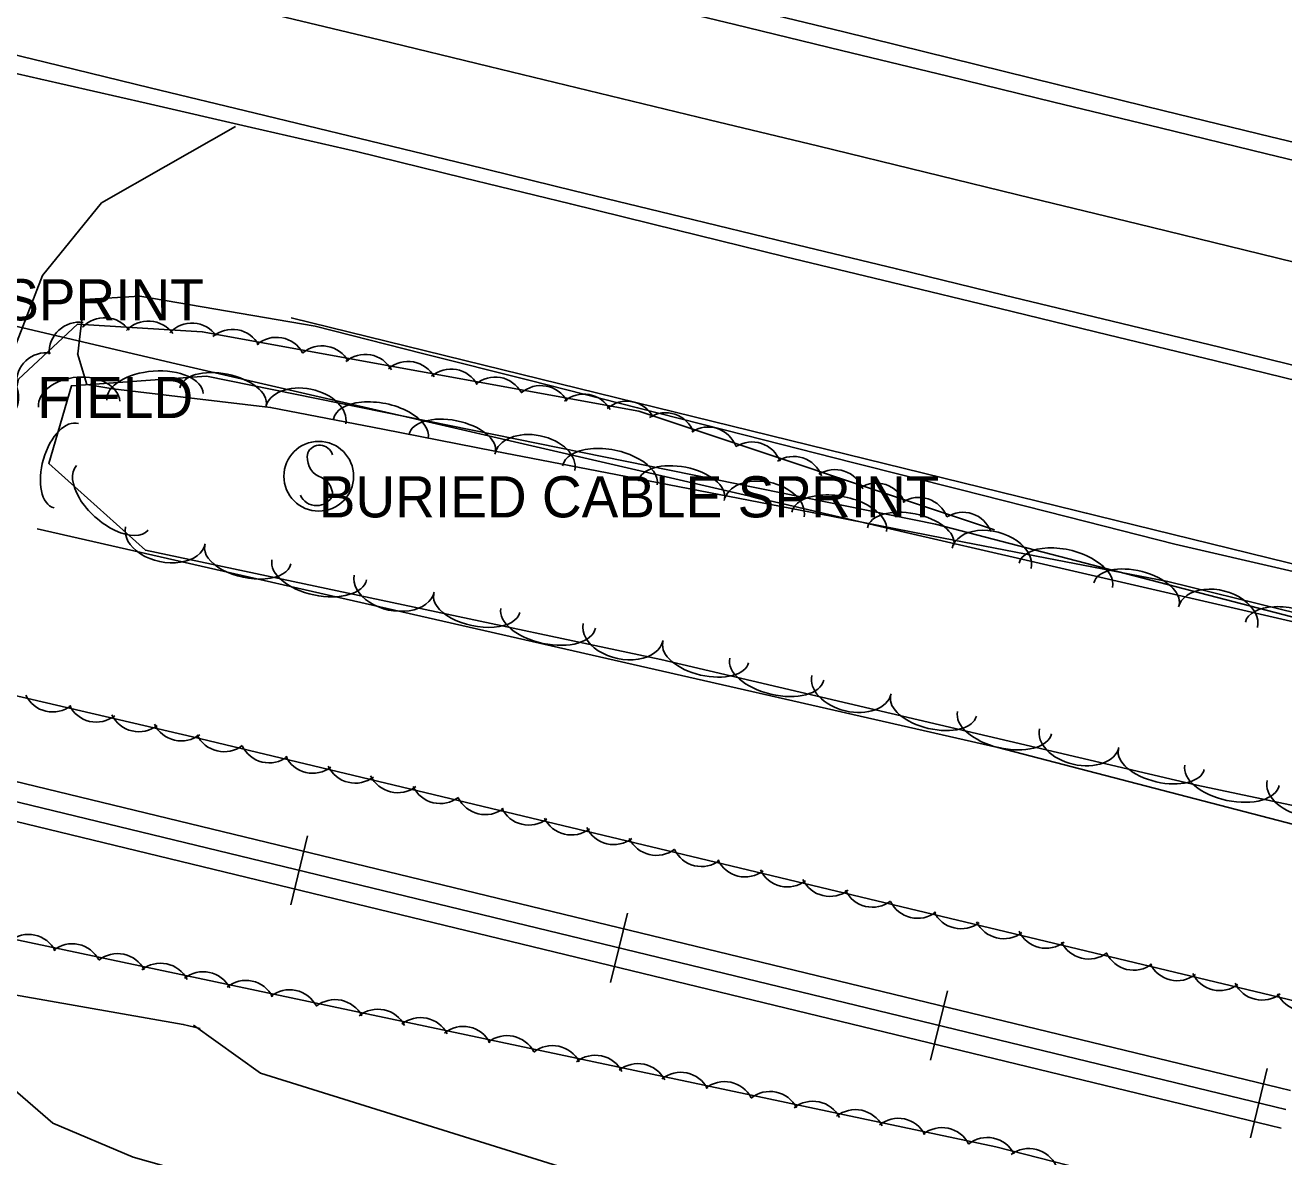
# Model space of a CAD drawing. Extents: x 1441650 to 1491889, y 345904 to 358319.
# Drawn here: x 1454238.7 to 1454391.6, y 352365.8 to 352503.4 of the extents above; entities that cross this region are included whole.
import ezdxf

# ---------------------------------------------------------------- set-up
doc = ezdxf.new("R2010")
doc.units = 0
for name, color, linetype in [('S_DITCHLINE', 7, 'Continuous'), ('S_EDGE_PAVEMENT', 7, 'Continuous'), ('S_GRAVEL_ROAD', 7, 'Continuous'), ('S_PAVEMENT_CROWN', 7, 'Continuous'), ('S_RAILROAD', 7, 'Continuous'), ('S_SHOULDER', 7, 'Continuous'), ('S_SIGN', 7, 'Continuous'), ('S_SIGN_ANNOT', 7, 'Continuous'), ('S_STREAM', 7, 'Continuous'), ('S_SURVEY_TEXT_ANNOT', 7, 'Continuous'), ('S_TREE', 7, 'Continuous')]:
    doc.layers.add(name, color=color, linetype=linetype)

msp = doc.modelspace()

# ---------------------------------------------------------------- linework, layer by layer
at = {"layer": 'S_DITCHLINE'}
for points in [[(1454245.06, 352463.43), (1454245.84, 352470.01), (1454252.59, 352470.4), (1454273.89, 352466.78), (1454286.95, 352463.47), (1454300.01, 352460.16), (1454313.07, 352456.85), (1454326.13, 352453.53), (1454339.19, 352450.22), (1454352.25, 352446.91), (1454365.31, 352443.6), (1454378.37, 352440.28), (1454392.2, 352437.07), (1454406.03, 352433.85), (1454419.86, 352430.64), (1454433.69, 352427.43), (1454447.53, 352424.21), (1454461.36, 352421), (1454475.19, 352417.78), (1454489.02, 352414.57), (1454502.88, 352411.14), (1454516.73, 352407.7), (1454530.58, 352404.27), (1454544.44, 352400.84)], [(1454245.03, 352463.46), (1454246.15, 352459.68), (1454249.29, 352459.16), (1454268.48, 352456.89), (1454282.11, 352454.24), (1454295.74, 352451.59), (1454309.36, 352448.95), (1454322.99, 352446.3), (1454336.62, 352443.66), (1454350.25, 352441.01), (1454363.88, 352438.36), (1454377.51, 352435.72), (1454391.33, 352432.35), (1454405.16, 352428.97), (1454418.98, 352425.6), (1454432.8, 352422.23), (1454446.63, 352418.85), (1454460.45, 352415.48), (1454474.27, 352412.11), (1454488.1, 352408.74), (1454501.74, 352404.67), (1454515.38, 352400.61), (1454529.02, 352396.55), (1454542.66, 352392.48)]]:
    msp.add_lwpolyline(points, dxfattribs=at)
at = {"layer": 'S_EDGE_PAVEMENT'}
for points in [[(1454234.14, 352525.39), (1454247.12, 352522.26), (1454260.09, 352519.12), (1454273.07, 352515.99), (1454286.04, 352512.86), (1454299, 352509.72), (1454311.95, 352506.58), (1454324.9, 352503.44), (1454337.85, 352500.29), (1454350.76, 352497.15), (1454363.67, 352494), (1454376.58, 352490.86), (1454389.49, 352487.72), (1454403.74, 352484.26), (1454417.98, 352480.8), (1454432.22, 352477.34), (1454446.47, 352473.88), (1454460.26, 352470.49), (1454474.05, 352467.09), (1454487.84, 352463.69), (1454501.63, 352460.3), (1454515.2, 352456.99), (1454528.77, 352453.68), (1454542.33, 352450.37)], [(1454228.36, 352501.94), (1454241.1, 352498.85), (1454253.85, 352495.76), (1454266.6, 352492.67), (1454279.34, 352489.58), (1454292.36, 352486.41), (1454305.38, 352483.24), (1454318.4, 352480.07), (1454331.42, 352476.9), (1454344.52, 352473.73), (1454357.63, 352470.56), (1454370.73, 352467.39), (1454383.83, 352464.22), (1454398.14, 352460.71)]]:
    msp.add_lwpolyline(points, dxfattribs=at)
at = {"layer": 'S_GRAVEL_ROAD'}
msp.add_lwpolyline([(1454228.71, 352431.22), (1454231.59, 352443.76), (1454235.46, 352459.28), (1454240.77, 352472.94), (1454247.94, 352481.75), (1454255.77, 352486.24), (1454264.22, 352491.06)], dxfattribs=at)
at = {"layer": 'S_PAVEMENT_CROWN'}
msp.add_lwpolyline([(1454232.36, 352513.43), (1454244.7, 352510.46), (1454257.04, 352507.5), (1454269.37, 352504.53), (1454281.71, 352501.57), (1454295.06, 352498.34), (1454308.41, 352495.1), (1454321.77, 352491.87), (1454335.12, 352488.64), (1454348.03, 352485.49), (1454360.94, 352482.34), (1454373.84, 352479.2), (1454386.75, 352476.05), (1454401.14, 352472.51), (1454415.53, 352468.97), (1454429.92, 352465.43), (1454444.3, 352461.89), (1454457.87, 352458.61), (1454471.44, 352455.33), (1454485.01, 352452.05), (1454498.58, 352448.77), (1454512.22, 352445.42), (1454525.86, 352442.07), (1454539.5, 352438.72)], dxfattribs=at)
at = {"layer": 'S_RAILROAD'}
for p, q in [((1454272.97, 352404.84), (1454270.92, 352396.42)), ((1454272.5, 352402.94), (1454272.5, 352402.9)), ((1454271.39, 352398.36), (1454271.42, 352398.46)), ((1454311.84, 352395.42), (1454309.8, 352386.99)), ((1454311.38, 352393.51), (1454311.37, 352393.47)), ((1454310.27, 352388.93), (1454310.29, 352389.03)), ((1454350.72, 352385.99), (1454348.67, 352377.56)), ((1454350.26, 352384.08), (1454350.25, 352384.04)), ((1454349.14, 352379.5), (1454349.17, 352379.6)), ((1454389.59, 352376.56), (1454387.55, 352368.13)), ((1454389.13, 352374.65), (1454389.12, 352374.62)), ((1454388.02, 352370.07), (1454388.04, 352370.18))]:
    msp.add_line(p, q, dxfattribs=at)
for points in [[(1453358.93, 352624.5), (1454392.41, 352373.86)], [(1453358.37, 352622.19), (1454391.85, 352371.55)], [(1453357.82, 352619.92), (1454391.3, 352369.28)], [(1454271.92, 352400.64), (1454271.94, 352400.63)], [(1454310.79, 352391.21), (1454310.82, 352391.2)], [(1454349.67, 352381.78), (1454349.7, 352381.77)], [(1454388.54, 352372.35), (1454388.57, 352372.35)]]:
    msp.add_lwpolyline(points, dxfattribs=at)
at = {"layer": 'S_SHOULDER'}
for points in [[(1454234.57, 352527.94), (1454247.57, 352524.71), (1454260.57, 352521.49), (1454273.57, 352518.26), (1454286.57, 352515.04), (1454299.46, 352511.92), (1454312.35, 352508.79), (1454325.23, 352505.67), (1454338.12, 352502.54), (1454351.1, 352499.35), (1454364.08, 352496.16), (1454377.06, 352492.96), (1454390.04, 352489.77), (1454404.56, 352486.31), (1454419.08, 352482.85), (1454433.6, 352479.39), (1454448.12, 352475.94), (1454461.64, 352472.57), (1454475.16, 352469.2), (1454488.69, 352465.83), (1454502.21, 352462.47), (1454515.71, 352459.14), (1454529.2, 352455.81), (1454542.7, 352452.48)], [(1454227.75, 352499.71), (1454240.54, 352496.78), (1454253.34, 352493.86), (1454266.14, 352490.93), (1454278.93, 352488), (1454291.92, 352484.82), (1454304.91, 352481.63), (1454317.9, 352478.45), (1454330.9, 352475.26), (1454344, 352472.08), (1454357.11, 352468.9), (1454370.22, 352465.72), (1454383.32, 352462.54), (1454397.69, 352459.04)]]:
    msp.add_lwpolyline(points, dxfattribs=at)
at = {"layer": 'S_SIGN'}
msp.add_circle((1454274.33, 352448.53), 4.24, dxfattribs=at)
for centre, radius, start, end in [((1454274.45, 352450.68), 1.62, 16.5258, 156.8957), ((1454275.49, 352450.78), 2.55, 167.1196, 241.9813), ((1454273.63, 352446.25), 2.38, 358.6529, 73.7063), ((1454274.07, 352447.13), 2.17, 204.641, 335.359)]:
    msp.add_arc(centre, radius, start, end, dxfattribs=at)
at = {"layer": 'S_STREAM'}
for points in [[(1454464.23, 352420.31), (1454270.96, 352467.8)], [(1454547.74, 352365.89), (1454356.85, 352415.58), (1454240.12, 352442.13)], [(1454388.13, 352330.44), (1454301.34, 352351.74), (1454251.8, 352365.75), (1454242.03, 352369.9), (1454232.87, 352377.8), (1454232.52, 352382.87), (1454237.35, 352385.48), (1454257.86, 352381.91), (1454259.92, 352381.42)], [(1454259.11, 352381.82), (1454267.25, 352375.97), (1454313.61, 352361.5), (1454369.24, 352347.29), (1454420.31, 352336.48), (1454471.98, 352326.31)]]:
    msp.add_lwpolyline(points, dxfattribs=at)
at = {"layer": 'S_TREE'}
for points in [[(1454448.79, 352371.34), (1454258.99, 352416.87), (1454236.55, 352422.09), (1454230.87, 352427.54), (1454232.8, 352437.08), (1454237.86, 352460.35), (1454245.03, 352467.03), (1454260.18, 352466.09), (1454313.24, 352456.44), (1454356.46, 352442.02)], [(1454233.67, 352467.68), (1454257.01, 352462.2), (1454271.76, 352458.79), (1454286.52, 352455.38), (1454301.27, 352451.98), (1454316.02, 352448.57), (1454330.77, 352445.16), (1454345.53, 352441.75), (1454360.28, 352438.34), (1454375.03, 352434.94), (1454389.78, 352431.53), (1454404.54, 352428.12), (1454419.29, 352424.71), (1454434.04, 352421.3), (1454448.79, 352417.9), (1454463.54, 352414.49), (1454478.3, 352411.08), (1454493.05, 352407.67), (1454507.8, 352404.26), (1454522.55, 352400.86), (1454537.31, 352397.45), (1454552.06, 352394.04)], [(1454233.67, 352467.68), (1454257.01, 352462.2), (1454271.76, 352458.79), (1454286.52, 352455.38), (1454301.27, 352451.98), (1454316.02, 352448.57), (1454330.77, 352445.16), (1454345.53, 352441.75), (1454360.28, 352438.34), (1454375.03, 352434.94), (1454389.78, 352431.53), (1454404.54, 352428.12), (1454419.29, 352424.71), (1454434.04, 352421.3), (1454448.79, 352417.9), (1454463.54, 352414.49), (1454478.3, 352411.08), (1454493.05, 352407.67), (1454507.8, 352404.26), (1454522.55, 352400.86), (1454537.31, 352397.45), (1454552.06, 352394.04)], [(1454454.43, 352395.45), (1454381.05, 352411), (1454315.92, 352426.27), (1454253.26, 352439.53), (1454241.52, 352450.08), (1454244.28, 352459.53), (1454260.7, 352460.69), (1454349.28, 352442.7), (1454478.07, 352409.22)], [(1454288.48, 352317.63), (1454252.91, 352329.03), (1454235.01, 352340.76), (1454221.11, 352357.5), (1454222.18, 352371.72), (1454225.51, 352387.52), (1454234.15, 352392.92), (1454356.62, 352367.02), (1454510.53, 352327.65), (1454613.3, 352304.23), (1454719.52, 352277.82)]]:
    msp.add_lwpolyline(points, dxfattribs=at)
for centre, major_axis, ratio, start_param, end_param in [((1454245.22, 352463.61), (-2.67, -2.48), 0.999994, 3.825789, 5.598989), ((1454248.31, 352464.16), (-3.64, 0.23), 0.999972, 3.825789, 5.598989), ((1454253.63, 352463.75), (-3.64, 0.23), 0.999972, 3.825789, 5.598989), ((1454258.91, 352463.5), (-3.64, 0.23), 0.999972, 3.825789, 5.598989), ((1454263.84, 352462.75), (-3.58, 0.65), 0.999971, 3.825789, 5.598989), ((1454269.19, 352461.78), (-3.58, 0.65), 0.999971, 3.825789, 5.598989), ((1454274.74, 352460.74), (-3.58, 0.65), 0.999971, 3.825789, 5.598989), ((1454241.23, 352459.9), (-2.67, -2.48), 0.999994, 3.825789, 5.598989), ((1454279.98, 352459.71), (-3.58, 0.65), 0.999971, 3.825789, 5.598989), ((1454285.19, 352458.84), (-3.58, 0.65), 0.999971, 3.825789, 5.598989), ((1454254.44, 352458.19), (-5.85, -0.41), 0.532441, 3.141593, 6.283185), ((1454262.7, 352458.2), (-5.24, 1.07), 0.521767, 3.145334, 6.286926), ((1454290.41, 352457.92), (-3.58, 0.65), 0.999971, 3.825789, 5.598989), ((1454245.22, 352457.29), (-4.94, -0.35), 0.663336, 3.141593, 6.283185), ((1454272.75, 352455.9), (-4.85, 1.01), 0.661307, 3.147726, 6.289318), ((1454295.77, 352456.95), (-3.58, 0.65), 0.999971, 3.825789, 5.598989), ((1454301.31, 352455.91), (-3.58, 0.65), 0.999971, 3.825789, 5.598989), ((1454281.87, 352454.3), (-5.75, 1.18), 0.530818, 3.145449, 6.287042), ((1454306.55, 352454.88), (-3.58, 0.65), 0.999971, 3.825789, 5.598989), ((1454311.76, 352454.01), (-3.58, 0.65), 0.999971, 3.825789, 5.598989), ((1454316.47, 352452.6), (-3.46, 1.15), 0.99997, 3.825789, 5.598989), ((1454243.65, 352449.81), (-1.49, -5.13), 0.540855, 3.141818, 6.28341), ((1454290.55, 352452.54), (-5.24, 1.07), 0.521767, 3.145334, 6.286926), ((1454300.6, 352450.24), (-4.85, 1.01), 0.661307, 3.147726, 6.289318), ((1454321.63, 352450.87), (-3.46, 1.15), 0.99997, 3.825789, 5.598989), ((1454309.72, 352448.64), (-5.75, 1.18), 0.530818, 3.145449, 6.287042), ((1454326.98, 352449.05), (-3.46, 1.15), 0.99997, 3.825789, 5.598989), ((1454332.02, 352447.29), (-3.46, 1.15), 0.99997, 3.825789, 5.598989), ((1454249.26, 352445.9), (4.37, -3.91), 0.535204, 3.135572, 6.277165), ((1454318.41, 352446.88), (-5.24, 1.07), 0.521767, 3.145334, 6.286926), ((1454337.05, 352445.69), (-3.46, 1.15), 0.99997, 3.825789, 5.598989), ((1454328.45, 352444.58), (-4.85, 1.01), 0.661307, 3.147726, 6.289318), ((1454342.09, 352444.05), (-3.46, 1.15), 0.99997, 3.825789, 5.598989), ((1454337.57, 352442.99), (-5.75, 1.18), 0.530818, 3.145449, 6.287042), ((1454347.25, 352442.32), (-3.46, 1.15), 0.99997, 3.825789, 5.598989), ((1454346.26, 352441.22), (-5.24, 1.07), 0.521767, 3.145334, 6.286926), ((1454352.6, 352440.5), (-3.46, 1.15), 0.99997, 3.825789, 5.598989), ((1454255.69, 352441.36), (4.85, -1.03), 0.661184, 3.141554, 6.283147), ((1454356.09, 352438.55), (-4.79, 1.27), 0.661267, 3.148013, 6.289606), ((1454265.72, 352438.98), (5.23, -1.11), 0.521664, 3.141569, 6.283162), ((1454365.11, 352436.47), (-5.68, 1.49), 0.530786, 3.14563, 6.287223), ((1454274.39, 352437.15), (5.74, -1.21), 0.530714, 3.141569, 6.283161), ((1454283.5, 352435.48), (4.85, -1.03), 0.661184, 3.141554, 6.283147), ((1454373.7, 352434.24), (-5.17, 1.36), 0.521735, 3.14551, 6.287102), ((1454383.6, 352431.4), (-4.79, 1.27), 0.661267, 3.148013, 6.289606), ((1454293.53, 352433.1), (5.23, -1.11), 0.521664, 3.141569, 6.283162), ((1454302.21, 352431.26), (5.74, -1.21), 0.530714, 3.141569, 6.283161), ((1454392.62, 352429.32), (-5.68, 1.49), 0.530786, 3.14563, 6.287223), ((1454311.32, 352429.59), (4.85, -1.03), 0.661184, 3.141554, 6.283147), ((1454321.36, 352427.09), (5.21, -1.22), 0.521646, 3.141593, 6.283185), ((1454329.99, 352425.07), (5.71, -1.34), 0.530696, 3.141593, 6.283185), ((1454339.07, 352423.2), (4.82, -1.13), 0.661161, 3.141593, 6.283185), ((1454242, 352423.52), (3.55, -0.82), 0.999971, 3.825789, 5.598989), ((1454349.04, 352420.6), (5.21, -1.22), 0.521646, 3.141593, 6.283185), ((1454247.3, 352422.29), (3.55, -0.82), 0.999971, 3.825789, 5.598989), ((1454252.47, 352421.12), (3.55, -0.82), 0.999971, 3.825789, 5.598989), ((1454357.67, 352418.58), (5.71, -1.34), 0.530696, 3.141593, 6.283185), ((1454257.63, 352420), (3.55, -0.82), 0.999971, 3.825789, 5.598989), ((1454262.83, 352418.69), (3.2, -1.74), 0.999968, 4.087876, 5.861077), ((1454366.74, 352416.71), (4.82, -1.13), 0.661161, 3.141593, 6.283185), ((1454268.31, 352417.34), (3.2, -1.74), 0.999968, 4.087876, 5.861077), ((1454376.72, 352414.11), (5.21, -1.22), 0.521646, 3.141593, 6.283185), ((1454273.6, 352416.07), (3.2, -1.74), 0.999968, 4.087876, 5.861077), ((1454385.32, 352412.18), (5.74, -1.22), 0.530714, 3.141593, 6.283185), ((1454278.77, 352414.87), (3.2, -1.74), 0.999968, 4.087876, 5.861077), ((1454283.92, 352413.71), (3.2, -1.74), 0.999968, 4.087876, 5.861077), ((1454289.09, 352412.39), (3.2, -1.74), 0.999968, 4.087876, 5.861077), ((1454394.43, 352410.51), (4.85, -1.03), 0.661184, 3.141593, 6.283185), ((1454294.57, 352411.04), (3.2, -1.74), 0.999968, 4.087876, 5.861077), ((1454299.86, 352409.77), (3.2, -1.74), 0.999968, 4.087876, 5.861077), ((1454305.03, 352408.57), (3.2, -1.74), 0.999968, 4.087876, 5.861077), ((1454310.18, 352407.4), (3.2, -1.74), 0.999968, 4.087876, 5.861077), ((1454315.35, 352406.09), (3.2, -1.74), 0.999968, 4.087876, 5.861077), ((1454320.84, 352404.74), (3.2, -1.74), 0.999968, 4.087876, 5.861077), ((1454326.13, 352403.47), (3.2, -1.74), 0.999968, 4.087876, 5.861077), ((1454331.29, 352402.26), (3.2, -1.74), 0.999968, 4.087876, 5.861077), ((1454336.45, 352401.1), (3.2, -1.74), 0.999968, 4.087876, 5.861077), ((1454341.62, 352399.79), (3.2, -1.74), 0.999968, 4.087876, 5.861077), ((1454347.1, 352398.44), (3.2, -1.74), 0.999968, 4.087876, 5.861077), ((1454352.39, 352397.17), (3.2, -1.74), 0.999968, 4.087876, 5.861077), ((1454357.56, 352395.96), (3.2, -1.74), 0.999968, 4.087876, 5.861077), ((1454239.06, 352389.2), (-0.97, 3.51), 0.999911, 4.917556, 6.690757), ((1454362.71, 352394.8), (3.2, -1.74), 0.999968, 4.087876, 5.861077), ((1454244.38, 352388.07), (-0.97, 3.51), 0.999911, 4.917556, 6.690757), ((1454249.89, 352386.87), (-0.97, 3.51), 0.999911, 4.917556, 6.690757), ((1454367.88, 352393.49), (3.2, -1.74), 0.999968, 4.087876, 5.861077), ((1454373.36, 352392.14), (3.2, -1.74), 0.999968, 4.087876, 5.861077), ((1454255.1, 352385.7), (-0.97, 3.51), 0.999911, 4.917556, 6.690757), ((1454378.65, 352390.86), (3.2, -1.74), 0.999968, 4.087876, 5.861077), ((1454260.28, 352384.67), (-0.97, 3.51), 0.999911, 4.917556, 6.690757), ((1454265.48, 352383.61), (-0.97, 3.51), 0.999911, 4.917556, 6.690757), ((1454383.82, 352389.66), (3.2, -1.74), 0.999968, 4.087876, 5.861077), ((1454270.8, 352382.48), (-0.97, 3.51), 0.999911, 4.917556, 6.690757), ((1454388.97, 352388.5), (3.2, -1.74), 0.999968, 4.087876, 5.861077), ((1454276.32, 352381.28), (-0.97, 3.51), 0.999911, 4.917556, 6.690757), ((1454394.14, 352387.19), (3.2, -1.74), 0.999968, 4.087876, 5.861077), ((1454281.52, 352380.11), (-0.97, 3.51), 0.999911, 4.917556, 6.690757), ((1454286.7, 352379.09), (-0.97, 3.51), 0.999911, 4.917556, 6.690757), ((1454291.9, 352378.02), (-0.97, 3.51), 0.999911, 4.917556, 6.690757), ((1454297.22, 352376.9), (-0.97, 3.51), 0.999911, 4.917556, 6.690757), ((1454302.74, 352375.69), (-0.97, 3.51), 0.999911, 4.917556, 6.690757), ((1454307.94, 352374.52), (-0.97, 3.51), 0.999911, 4.917556, 6.690757), ((1454313.13, 352373.5), (-0.97, 3.51), 0.999911, 4.917556, 6.690757), ((1454318.32, 352372.44), (-0.97, 3.51), 0.999911, 4.917556, 6.690757), ((1454323.64, 352371.31), (-0.97, 3.51), 0.999911, 4.917556, 6.690757), ((1454329.16, 352370.11), (-0.97, 3.51), 0.999911, 4.917556, 6.690757), ((1454334.37, 352368.93), (-0.97, 3.51), 0.999911, 4.917556, 6.690757), ((1454339.55, 352367.91), (-0.97, 3.51), 0.999911, 4.917556, 6.690757), ((1454344.74, 352366.85), (-0.97, 3.51), 0.999911, 4.917556, 6.690757), ((1454350.07, 352365.72), (-0.97, 3.51), 0.999911, 4.917556, 6.690757), ((1454355.58, 352364.52), (-0.97, 3.51), 0.999911, 4.917556, 6.690757), ((1454360.63, 352363.17), (-2.97, -2.12), 0.999955, 2.955422, 4.728623)]:
    msp.add_ellipse(centre, major_axis=major_axis, ratio=ratio, start_param=start_param, end_param=end_param, dxfattribs=at)

# ---------------------------------------------------------------- texts
at = {"layer": 'S_SIGN_ANNOT'}
for s, p in [('BARRIED CABLE SPRINT', (1454180.49, 352467.48)), ('BURIED CABLE SPRINT', (1454274.33, 352443.53))]:
    msp.add_text(s, height=5, dxfattribs=at).set_placement(p)
at = {"layer": 'S_SURVEY_TEXT_ANNOT'}
msp.add_text('TO FIELD', height=5, dxfattribs=at).set_placement((1454228.99, 352455.61))

doc.saveas('drawing.dxf')
